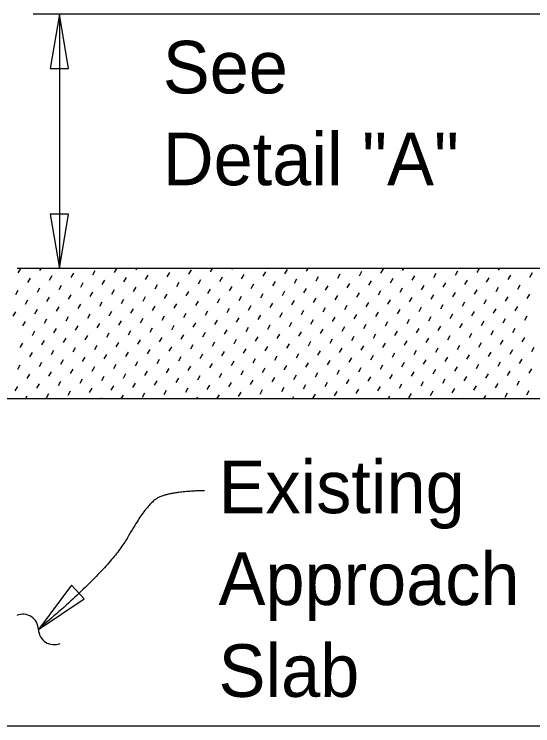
# Model space of a CAD drawing. Extents: x 21516.9 to 21589, y 56156.6 to 56194.3.
# Drawn here: x 21543.323 to 21545.311, y 56181.459 to 56184.186 of the extents above; entities that cross this region are included whole.
import ezdxf

# ---------------------------------------------------------------- set-up
doc = ezdxf.new("R2010")
doc.units = 0
for name, color, linetype in [('AdhocPoint_dp', 7, 'Continuous'), ('Patterning', 7, 'Continuous'), ('PlotBorder_dp', 7, 'Continuous'), ('SheetBorder_dp', 7, 'Continuous')]:
    doc.layers.add(name, color=color, linetype=linetype)

msp = doc.modelspace()

# ---------------------------------------------------------------- linework, layer by layer
at = {"layer": 'AdhocPoint_dp'}
for p, q in [((21545.7957, 56182.7117), (21541.8624, 56182.7117)), ((21541.8624, 56181.4587), (21548.1773, 56181.4587))]:
    msp.add_line(p, q, dxfattribs=at)
at = {"layer": 'Patterning'}
for p, q in [((21545.8544, 56183.2117), (21543.3336, 56183.2117)), ((21543.3386, 56183.1944), (21543.3483, 56183.2112)), ((21543.4215, 56183.2041), (21543.4259, 56183.2117)), ((21543.707, 56183.1967), (21543.7157, 56183.2117)), ((21543.7899, 56183.2064), (21543.793, 56183.2117)), ((21544.0753, 56183.199), (21544.0827, 56183.2117)), ((21544.1582, 56183.2087), (21544.16, 56183.2117)), ((21544.3607, 56183.1915), (21544.3705, 56183.2083)), ((21544.4437, 56183.2013), (21544.4497, 56183.2117)), ((21544.5266, 56183.211), (21544.527, 56183.2117)), ((21544.7291, 56183.1938), (21544.7388, 56183.2106)), ((21544.812, 56183.2035), (21544.8168, 56183.2117)), ((21545.0974, 56183.1961), (21545.1065, 56183.2117)), ((21545.1804, 56183.2058), (21545.1838, 56183.2117)), ((21543.4581, 56183.1675), (21543.4679, 56183.1843)), ((21543.5411, 56183.1773), (21543.5508, 56183.194)), ((21543.624, 56183.187), (21543.6337, 56183.2038)), ((21543.8265, 56183.1698), (21543.8362, 56183.1866)), ((21543.9094, 56183.1795), (21543.9192, 56183.1963)), ((21543.9924, 56183.1893), (21544.0021, 56183.2061)), ((21544.1949, 56183.1721), (21544.2046, 56183.1889)), ((21544.2778, 56183.1818), (21544.2875, 56183.1986)), ((21544.4803, 56183.1647), (21544.49, 56183.1814)), ((21544.5632, 56183.1744), (21544.5729, 56183.1912)), ((21544.6462, 56183.1841), (21544.6559, 56183.2009)), ((21544.8486, 56183.1669), (21544.8584, 56183.1837)), ((21544.9316, 56183.1767), (21544.9413, 56183.1935)), ((21545.0145, 56183.1864), (21545.0242, 56183.2032)), ((21545.217, 56183.1692), (21545.2267, 56183.186)), ((21545.2999, 56183.1789), (21545.3097, 56183.1957)), ((21543.3752, 56183.1578), (21543.3849, 56183.1746)), ((21543.5777, 56183.1406), (21543.5874, 56183.1574)), ((21543.6606, 56183.1504), (21543.6703, 56183.1672)), ((21543.7436, 56183.1601), (21543.7533, 56183.1769)), ((21543.946, 56183.1429), (21543.9558, 56183.1597)), ((21544.029, 56183.1526), (21544.0387, 56183.1694)), ((21544.1119, 56183.1624), (21544.1216, 56183.1792)), ((21544.3144, 56183.1452), (21544.3241, 56183.162)), ((21544.3973, 56183.1549), (21544.4071, 56183.1717)), ((21544.5998, 56183.1378), (21544.6095, 56183.1546)), ((21544.6828, 56183.1475), (21544.6925, 56183.1643)), ((21544.7657, 56183.1572), (21544.7754, 56183.174)), ((21544.9682, 56183.1401), (21544.9779, 56183.1568)), ((21545.0511, 56183.1498), (21545.0608, 56183.1666)), ((21545.1341, 56183.1595), (21545.1438, 56183.1763)), ((21543.3289, 56183.1115), (21543.3386, 56183.1283)), ((21543.4118, 56183.1212), (21543.4215, 56183.138)), ((21543.4947, 56183.1309), (21543.5045, 56183.1477)), ((21543.6972, 56183.1138), (21543.707, 56183.1306)), ((21543.7802, 56183.1235), (21543.7899, 56183.1403)), ((21543.8631, 56183.1332), (21543.8728, 56183.15)), ((21544.0656, 56183.116), (21544.0753, 56183.1328)), ((21544.1485, 56183.1258), (21544.1582, 56183.1426)), ((21544.2315, 56183.1355), (21544.2412, 56183.1523)), ((21544.4339, 56183.1183), (21544.4437, 56183.1351)), ((21544.5169, 56183.128), (21544.5266, 56183.1448)), ((21544.7194, 56183.1109), (21544.7291, 56183.1277)), ((21544.8023, 56183.1206), (21544.812, 56183.1374)), ((21544.8852, 56183.1303), (21544.895, 56183.1471)), ((21545.0877, 56183.1132), (21545.0974, 56183.13)), ((21545.1707, 56183.1229), (21545.1804, 56183.1397)), ((21545.2536, 56183.1326), (21545.2633, 56183.1494)), ((21543.4484, 56183.0846), (21543.4581, 56183.1014)), ((21543.5314, 56183.0943), (21543.5411, 56183.1111)), ((21543.6143, 56183.104), (21543.624, 56183.1208)), ((21543.8168, 56183.0869), (21543.8265, 56183.1037)), ((21543.8997, 56183.0966), (21543.9094, 56183.1134)), ((21543.9827, 56183.1063), (21543.9924, 56183.1231)), ((21544.1851, 56183.0892), (21544.1949, 56183.106)), ((21544.2681, 56183.0989), (21544.2778, 56183.1157)), ((21544.351, 56183.1086), (21544.3607, 56183.1254)), ((21544.5535, 56183.0914), (21544.5632, 56183.1082)), ((21544.6364, 56183.1012), (21544.6462, 56183.118)), ((21544.8389, 56183.084), (21544.8486, 56183.1008)), ((21544.9219, 56183.0937), (21544.9316, 56183.1105)), ((21545.0048, 56183.1034), (21545.0145, 56183.1202)), ((21545.2073, 56183.0863), (21545.217, 56183.1031)), ((21545.2902, 56183.096), (21545.2999, 56183.1128)), ((21543.3655, 56183.0749), (21543.3752, 56183.0917)), ((21543.568, 56183.0577), (21543.5777, 56183.0745)), ((21543.6509, 56183.0674), (21543.6606, 56183.0842)), ((21543.7338, 56183.0772), (21543.7436, 56183.0939)), ((21543.9363, 56183.06), (21543.946, 56183.0768)), ((21544.0193, 56183.0697), (21544.029, 56183.0865)), ((21544.1022, 56183.0794), (21544.1119, 56183.0962)), ((21544.3047, 56183.0623), (21544.3144, 56183.0791)), ((21544.3876, 56183.072), (21544.3973, 56183.0888)), ((21544.4706, 56183.0817), (21544.4803, 56183.0985)), ((21544.5901, 56183.0548), (21544.5998, 56183.0716)), ((21544.673, 56183.0646), (21544.6828, 56183.0813)), ((21544.756, 56183.0743), (21544.7657, 56183.0911)), ((21544.9585, 56183.0571), (21544.9682, 56183.0739)), ((21545.0414, 56183.0668), (21545.0511, 56183.0836)), ((21545.1243, 56183.0766), (21545.1341, 56183.0934)), ((21543.3191, 56183.0285), (21543.3289, 56183.0453)), ((21543.4021, 56183.0383), (21543.4118, 56183.0551)), ((21543.485, 56183.048), (21543.4947, 56183.0648)), ((21543.6875, 56183.0308), (21543.6972, 56183.0476)), ((21543.7704, 56183.0405), (21543.7802, 56183.0573)), ((21543.8534, 56183.0503), (21543.8631, 56183.0671)), ((21544.0559, 56183.0331), (21544.0656, 56183.0499)), ((21544.1388, 56183.0428), (21544.1485, 56183.0596)), ((21544.2217, 56183.0525), (21544.2315, 56183.0693)), ((21544.4242, 56183.0354), (21544.4339, 56183.0522)), ((21544.5072, 56183.0451), (21544.5169, 56183.0619)), ((21544.7096, 56183.0279), (21544.7194, 56183.0447)), ((21544.7926, 56183.0377), (21544.8023, 56183.0545)), ((21544.8755, 56183.0474), (21544.8852, 56183.0642)), ((21545.078, 56183.0302), (21545.0877, 56183.047)), ((21545.1609, 56183.04), (21545.1707, 56183.0567)), ((21545.2439, 56183.0497), (21545.2536, 56183.0665)), ((21543.4387, 56183.0017), (21543.4484, 56183.0184)), ((21543.5216, 56183.0114), (21543.5314, 56183.0282)), ((21543.6046, 56183.0211), (21543.6143, 56183.0379)), ((21543.8071, 56183.0039), (21543.8168, 56183.0207)), ((21543.89, 56183.0137), (21543.8997, 56183.0305)), ((21543.9729, 56183.0234), (21543.9827, 56183.0402)), ((21544.1754, 56183.0062), (21544.1851, 56183.023)), ((21544.2583, 56183.0159), (21544.2681, 56183.0327)), ((21544.3413, 56183.0257), (21544.351, 56183.0425)), ((21544.5438, 56183.0085), (21544.5535, 56183.0253)), ((21544.6267, 56183.0182), (21544.6364, 56183.035)), ((21544.8292, 56183.0011), (21544.8389, 56183.0179)), ((21544.9121, 56183.0108), (21544.9219, 56183.0276)), ((21544.9951, 56183.0205), (21545.0048, 56183.0373)), ((21545.1975, 56183.0033), (21545.2073, 56183.0201)), ((21545.2805, 56183.0131), (21545.2902, 56183.0299)), ((21543.3558, 56182.9919), (21543.3655, 56183.0087)), ((21543.5582, 56182.9748), (21543.568, 56182.9916)), ((21543.6412, 56182.9845), (21543.6509, 56183.0013)), ((21543.7241, 56182.9942), (21543.7338, 56183.011)), ((21543.9266, 56182.9771), (21543.9363, 56182.9938)), ((21544.0095, 56182.9868), (21544.0193, 56183.0036)), ((21544.0925, 56182.9965), (21544.1022, 56183.0133)), ((21544.295, 56182.9793), (21544.3047, 56182.9961)), ((21544.3779, 56182.9891), (21544.3876, 56183.0059)), ((21544.4608, 56182.9988), (21544.4706, 56183.0156)), ((21544.6633, 56182.9816), (21544.673, 56182.9984)), ((21544.7463, 56182.9913), (21544.756, 56183.0081)), ((21544.9487, 56182.9742), (21544.9585, 56182.991)), ((21545.0317, 56182.9839), (21545.0414, 56183.0007)), ((21545.1146, 56182.9936), (21545.1243, 56183.0104)), ((21543.3924, 56182.9553), (21543.4021, 56182.9721)), ((21543.4753, 56182.965), (21543.485, 56182.9818)), ((21543.6778, 56182.9479), (21543.6875, 56182.9647)), ((21543.7607, 56182.9576), (21543.7704, 56182.9744)), ((21543.8437, 56182.9673), (21543.8534, 56182.9841)), ((21544.0461, 56182.9502), (21544.0559, 56182.967)), ((21544.1291, 56182.9599), (21544.1388, 56182.9767)), ((21544.212, 56182.9696), (21544.2217, 56182.9864)), ((21544.4145, 56182.9525), (21544.4242, 56182.9692)), ((21544.4974, 56182.9622), (21544.5072, 56182.979)), ((21544.5804, 56182.9719), (21544.5901, 56182.9887)), ((21544.7829, 56182.9547), (21544.7926, 56182.9715)), ((21544.8658, 56182.9645), (21544.8755, 56182.9812)), ((21545.0683, 56182.9473), (21545.078, 56182.9641)), ((21545.1512, 56182.957), (21545.1609, 56182.9738)), ((21545.2342, 56182.9667), (21545.2439, 56182.9835)), ((21543.429, 56182.9187), (21543.4387, 56182.9355)), ((21543.5119, 56182.9284), (21543.5216, 56182.9452)), ((21543.5948, 56182.9382), (21543.6046, 56182.955)), ((21543.7973, 56182.921), (21543.8071, 56182.9378)), ((21543.8803, 56182.9307), (21543.89, 56182.9475)), ((21543.9632, 56182.9404), (21543.9729, 56182.9572)), ((21544.1657, 56182.9233), (21544.1754, 56182.9401)), ((21544.2486, 56182.933), (21544.2583, 56182.9498)), ((21544.3316, 56182.9427), (21544.3413, 56182.9595)), ((21544.534, 56182.9256), (21544.5438, 56182.9424)), ((21544.617, 56182.9353), (21544.6267, 56182.9521)), ((21544.6999, 56182.945), (21544.7096, 56182.9618)), ((21544.8195, 56182.9181), (21544.8292, 56182.9349)), ((21544.9024, 56182.9278), (21544.9121, 56182.9446)), ((21544.9853, 56182.9376), (21544.9951, 56182.9544)), ((21545.1878, 56182.9204), (21545.1975, 56182.9372)), ((21545.2708, 56182.9301), (21545.2805, 56182.9469)), ((21543.346, 56182.909), (21543.3558, 56182.9258)), ((21543.5485, 56182.8918), (21543.5582, 56182.9086)), ((21543.6315, 56182.9016), (21543.6412, 56182.9183)), ((21543.7144, 56182.9113), (21543.7241, 56182.9281)), ((21543.9169, 56182.8941), (21543.9266, 56182.9109)), ((21543.9998, 56182.9038), (21544.0095, 56182.9206)), ((21544.0828, 56182.9136), (21544.0925, 56182.9304)), ((21544.2852, 56182.8964), (21544.295, 56182.9132)), ((21544.3682, 56182.9061), (21544.3779, 56182.9229)), ((21544.4511, 56182.9158), (21544.4608, 56182.9326)), ((21544.6536, 56182.8987), (21544.6633, 56182.9155)), ((21544.7365, 56182.9084), (21544.7463, 56182.9252)), ((21544.939, 56182.8912), (21544.9487, 56182.908)), ((21545.022, 56182.901), (21545.0317, 56182.9178)), ((21545.1049, 56182.9107), (21545.1146, 56182.9275)), ((21545.3074, 56182.8935), (21545.3171, 56182.9103)), ((21543.3826, 56182.8724), (21543.3924, 56182.8892)), ((21543.4656, 56182.8821), (21543.4753, 56182.8989)), ((21543.6681, 56182.8649), (21543.6778, 56182.8817)), ((21543.751, 56182.8747), (21543.7607, 56182.8915)), ((21543.8339, 56182.8844), (21543.8437, 56182.9012)), ((21544.0364, 56182.8672), (21544.0461, 56182.884)), ((21544.1194, 56182.877), (21544.1291, 56182.8937)), ((21544.2023, 56182.8867), (21544.212, 56182.9035)), ((21544.4048, 56182.8695), (21544.4145, 56182.8863)), ((21544.4877, 56182.8792), (21544.4974, 56182.896)), ((21544.5707, 56182.889), (21544.5804, 56182.9058)), ((21544.7731, 56182.8718), (21544.7829, 56182.8886)), ((21544.8561, 56182.8815), (21544.8658, 56182.8983)), ((21545.0586, 56182.8644), (21545.0683, 56182.8812)), ((21545.1415, 56182.8741), (21545.1512, 56182.8909)), ((21545.2244, 56182.8838), (21545.2342, 56182.9006)), ((21543.5022, 56182.8455), (21543.5119, 56182.8623)), ((21543.5851, 56182.8552), (21543.5948, 56182.872)), ((21543.7876, 56182.8381), (21543.7973, 56182.8549)), ((21543.8705, 56182.8478), (21543.8803, 56182.8646)), ((21543.9535, 56182.8575), (21543.9632, 56182.8743)), ((21544.156, 56182.8403), (21544.1657, 56182.8571)), ((21544.2389, 56182.8501), (21544.2486, 56182.8669)), ((21544.3218, 56182.8598), (21544.3316, 56182.8766)), ((21544.5243, 56182.8426), (21544.534, 56182.8594)), ((21544.6073, 56182.8524), (21544.617, 56182.8691)), ((21544.6902, 56182.8621), (21544.6999, 56182.8789)), ((21544.8927, 56182.8449), (21544.9024, 56182.8617)), ((21544.9756, 56182.8546), (21544.9853, 56182.8714)), ((21545.1781, 56182.8375), (21545.1878, 56182.8543)), ((21545.261, 56182.8472), (21545.2708, 56182.864)), ((21543.3363, 56182.8261), (21543.346, 56182.8428)), ((21543.4192, 56182.8358), (21543.429, 56182.8526)), ((21543.6217, 56182.8186), (21543.6315, 56182.8354)), ((21543.7047, 56182.8283), (21543.7144, 56182.8451)), ((21543.9072, 56182.8112), (21543.9169, 56182.828)), ((21543.9901, 56182.8209), (21543.9998, 56182.8377)), ((21544.073, 56182.8306), (21544.0828, 56182.8474)), ((21544.2755, 56182.8135), (21544.2852, 56182.8303)), ((21544.3584, 56182.8232), (21544.3682, 56182.84)), ((21544.4414, 56182.8329), (21544.4511, 56182.8497)), ((21544.6439, 56182.8157), (21544.6536, 56182.8325)), ((21544.7268, 56182.8255), (21544.7365, 56182.8423)), ((21544.8097, 56182.8352), (21544.8195, 56182.852)), ((21545.0122, 56182.818), (21545.022, 56182.8348)), ((21545.0952, 56182.8277), (21545.1049, 56182.8445)), ((21545.2976, 56182.8106), (21545.3074, 56182.8274)), ((21543.3729, 56182.7894), (21543.3826, 56182.8062)), ((21543.4559, 56182.7992), (21543.4656, 56182.816)), ((21543.5388, 56182.8089), (21543.5485, 56182.8257)), ((21543.6583, 56182.782), (21543.6681, 56182.7988)), ((21543.7413, 56182.7917), (21543.751, 56182.8085)), ((21543.8242, 56182.8015), (21543.8339, 56182.8182)), ((21544.0267, 56182.7843), (21544.0364, 56182.8011)), ((21544.1096, 56182.794), (21544.1194, 56182.8108)), ((21544.1926, 56182.8037), (21544.2023, 56182.8205)), ((21544.3951, 56182.7866), (21544.4048, 56182.8034)), ((21544.478, 56182.7963), (21544.4877, 56182.8131)), ((21544.5609, 56182.806), (21544.5707, 56182.8228)), ((21544.7634, 56182.7889), (21544.7731, 56182.8057)), ((21544.8464, 56182.7986), (21544.8561, 56182.8154)), ((21544.9293, 56182.8083), (21544.939, 56182.8251)), ((21545.1318, 56182.7911), (21545.1415, 56182.8079)), ((21545.2147, 56182.8009), (21545.2244, 56182.8177)), ((21543.4925, 56182.7626), (21543.5022, 56182.7794)), ((21543.5754, 56182.7723), (21543.5851, 56182.7891)), ((21543.7779, 56182.7551), (21543.7876, 56182.7719)), ((21543.8608, 56182.7648), (21543.8705, 56182.7816)), ((21543.9438, 56182.7746), (21543.9535, 56182.7914)), ((21544.1462, 56182.7574), (21544.156, 56182.7742)), ((21544.2292, 56182.7671), (21544.2389, 56182.7839)), ((21544.3121, 56182.7769), (21544.3218, 56182.7936)), ((21544.5146, 56182.7597), (21544.5243, 56182.7765)), ((21544.5975, 56182.7694), (21544.6073, 56182.7862)), ((21544.6805, 56182.7791), (21544.6902, 56182.7959)), ((21544.883, 56182.762), (21544.8927, 56182.7788)), ((21544.9659, 56182.7717), (21544.9756, 56182.7885)), ((21545.0488, 56182.7814), (21545.0586, 56182.7982)), ((21545.1684, 56182.7545), (21545.1781, 56182.7713)), ((21545.2513, 56182.7643), (21545.261, 56182.7811)), ((21543.3266, 56182.7431), (21543.3363, 56182.7599)), ((21543.4095, 56182.7528), (21543.4192, 56182.7696)), ((21543.612, 56182.7357), (21543.6217, 56182.7525)), ((21543.6949, 56182.7454), (21543.7047, 56182.7622)), ((21543.8974, 56182.7282), (21543.9072, 56182.745)), ((21543.9804, 56182.738), (21543.9901, 56182.7548)), ((21544.0633, 56182.7477), (21544.073, 56182.7645)), ((21544.2658, 56182.7305), (21544.2755, 56182.7473)), ((21544.3487, 56182.7402), (21544.3584, 56182.757)), ((21544.4317, 56182.75), (21544.4414, 56182.7668)), ((21544.6341, 56182.7328), (21544.6439, 56182.7496)), ((21544.7171, 56182.7425), (21544.7268, 56182.7593)), ((21544.8, 56182.7523), (21544.8097, 56182.769)), ((21545.0025, 56182.7351), (21545.0122, 56182.7519)), ((21545.0854, 56182.7448), (21545.0952, 56182.7616)), ((21545.2879, 56182.7276), (21545.2976, 56182.7444)), ((21543.3662, 56182.7117), (21543.3729, 56182.7233)), ((21543.4461, 56182.7162), (21543.4559, 56182.733)), ((21543.5291, 56182.726), (21543.5388, 56182.7427)), ((21543.7333, 56182.7117), (21543.7413, 56182.7256)), ((21543.8145, 56182.7185), (21543.8242, 56182.7353)), ((21544.023, 56182.7117), (21544.0267, 56182.7181)), ((21544.1003, 56182.7117), (21544.1096, 56182.7279)), ((21544.1829, 56182.7208), (21544.1926, 56182.7376)), ((21544.39, 56182.7117), (21544.3951, 56182.7204)), ((21544.4683, 56182.7134), (21544.478, 56182.7302)), ((21544.5512, 56182.7231), (21544.5609, 56182.7399)), ((21544.7571, 56182.7117), (21544.7634, 56182.7227)), ((21544.8366, 56182.7156), (21544.8464, 56182.7324)), ((21544.9196, 56182.7254), (21544.9293, 56182.7422)), ((21545.1241, 56182.7117), (21545.1318, 56182.725)), ((21545.205, 56182.7179), (21545.2147, 56182.7347)), ((21543.656, 56182.7117), (21543.6583, 56182.7159)), ((21544.6798, 56182.7117), (21544.6805, 56182.713)), ((21545.0468, 56182.7117), (21545.0488, 56182.7153))]:
    msp.add_line(p, q, dxfattribs=at)
at = {"layer": 'PlotBorder_dp'}
for p, q in [((21545.8933, 56184.1864), (21543.3961, 56184.1864)), ((21543.4961, 56184.1864), (21543.4961, 56183.2117))]:
    msp.add_line(p, q, dxfattribs=at)
for points in [[(21543.4961, 56184.1864), (21543.4608, 56183.9781), (21543.5313, 56183.9781)], [(21543.4961, 56183.2117), (21543.5313, 56183.42), (21543.4608, 56183.42)], [(21543.4154, 56181.8283), (21543.5908, 56181.9459), (21543.5423, 56181.9971)]]:
    msp.add_lwpolyline(points, close=True, dxfattribs=at)
for centre, start, end in [((21543.3563, 56181.8265), 1.3261, 113.0533), ((21543.4755, 56181.8293), 181.3261, 293.0533)]:
    msp.add_arc(centre, 0.0596, start, end, dxfattribs=at)
msp.add_open_spline([(21544.0519, 56182.3599), (21543.9186, 56182.3565), (21543.8297, 56182.3086), (21543.6895, 56182.0589), (21543.4154, 56181.8283)], degree=2, dxfattribs=at)

# ---------------------------------------------------------------- texts
for s, p in [('Existing ', (21544.1064, 56182.2735)), ('Approach ', (21544.1064, 56181.9215)), ('Slab', (21544.1064, 56181.5695))]:
    msp.add_text(s, height=0.2016, dxfattribs=at).set_placement(p)
at = {"layer": 'SheetBorder_dp'}
for s, p in [('See ', (21543.8927, 56183.8828)), ('Detail "A" ', (21543.8927, 56183.5308))]:
    msp.add_text(s, height=0.2016, dxfattribs=at).set_placement(p)

doc.saveas('drawing.dxf')
